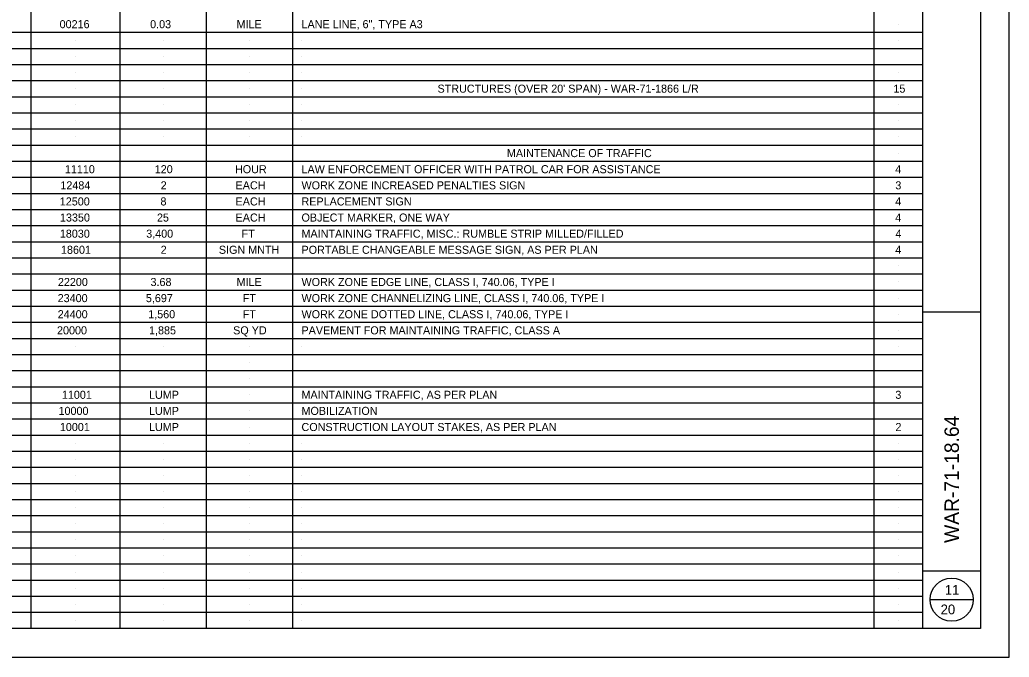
# Model space of a CAD drawing. Extents: x 1 to 35, y -2 to 20.
# Drawn here: x 17.83 to 35.03, y -1.96 to 9.12 of the extents above; entities that cross this region are included whole.
import ezdxf

# ---------------------------------------------------------------- set-up
doc = ezdxf.new("R2010")
doc.units = 0
for name, color, linetype in [('SH_Border', 7, 'Continuous'), ('SH_Cut_Line', 7, 'Continuous'), ('SH_Data', 7, 'Continuous'), ('SH_Text', 7, 'Continuous')]:
    doc.layers.add(name, color=color, linetype=linetype)

msp = doc.modelspace()

# ---------------------------------------------------------------- linework, layer by layer
at = {"layer": 'SH_Border'}
for p, q in [((33.531, -1.457), (33.531, 19.543)), ((33.531, 4.043), (34.531, 4.043)), ((33.531, -0.457), (34.531, -0.457))]:
    msp.add_line(p, q, dxfattribs=at)
msp.add_lwpolyline([(3.031, 19.543), (34.531, 19.543), (34.531, -1.457), (3.031, -1.457)], close=True, dxfattribs=at)
at = {"layer": 'SH_Cut_Line'}
msp.add_lwpolyline([(1.031, -1.957), (35.031, -1.957), (35.031, 20.043), (1.031, 20.043)], close=True, dxfattribs=at)
at = {"layer": 'SH_Data'}
for p, q in [((18.031, -1.457), (18.031, 19.543)), ((19.581, -1.457), (19.581, 19.543)), ((21.081, -1.457), (21.081, 19.543)), ((22.581, -1.457), (22.581, 19.543)), ((32.681, -1.457), (32.681, 19.543)), ((18.806, 9.043), (18.806, 9.043)), ((18.806, 9.043), (18.806, 9.043)), ((20.331, 9.043), (20.331, 9.043)), ((20.331, 9.043), (20.331, 9.043)), ((21.831, 9.043), (21.831, 9.043)), ((21.831, 9.043), (21.831, 9.043)), ((22.731, 9.043), (22.731, 9.043)), ((22.731, 9.043), (22.731, 9.043)), ((33.106, 9.043), (33.106, 9.043)), ((3.031, 8.903), (33.531, 8.903)), ((3.031, 8.623), (33.531, 8.623)), ((18.806, 8.763), (18.806, 8.763)), ((20.331, 8.763), (20.331, 8.763)), ((21.831, 8.763), (21.831, 8.763)), ((22.731, 8.763), (22.731, 8.763)), ((33.106, 8.763), (33.106, 8.763)), ((18.806, 8.483), (18.806, 8.483)), ((20.331, 8.483), (20.331, 8.483)), ((21.831, 8.483), (21.831, 8.483)), ((22.731, 8.483), (22.731, 8.483)), ((3.031, 8.343), (33.531, 8.343)), ((18.806, 8.203), (18.806, 8.203)), ((20.331, 8.203), (20.331, 8.203)), ((21.831, 8.203), (21.831, 8.203)), ((22.731, 8.203), (22.731, 8.203)), ((33.106, 8.203), (33.106, 8.203)), ((3.031, 8.063), (33.531, 8.063)), ((18.806, 7.923), (18.806, 7.923)), ((20.331, 7.923), (20.331, 7.923)), ((21.831, 7.923), (21.831, 7.923)), ((22.731, 7.923), (22.731, 7.923)), ((33.106, 7.923), (33.106, 7.923)), ((3.031, 7.783), (33.531, 7.783)), ((18.806, 7.643), (18.806, 7.643)), ((20.331, 7.643), (20.331, 7.643)), ((21.831, 7.643), (21.831, 7.643)), ((22.731, 7.643), (22.731, 7.643)), ((33.106, 7.643), (33.106, 7.643)), ((3.031, 7.503), (33.531, 7.503)), ((3.031, 7.223), (33.531, 7.223)), ((18.806, 7.363), (18.806, 7.363)), ((20.331, 7.363), (20.331, 7.363)), ((21.831, 7.363), (21.831, 7.363)), ((22.731, 7.363), (22.731, 7.363)), ((33.106, 7.363), (33.106, 7.363)), ((18.806, 7.083), (18.806, 7.083)), ((20.331, 7.083), (20.331, 7.083)), ((21.831, 7.083), (21.831, 7.083)), ((22.731, 7.083), (22.731, 7.083)), ((33.106, 7.083), (33.106, 7.083)), ((3.031, 6.943), (33.531, 6.943)), ((33.106, 6.803), (33.106, 6.803)), ((3.031, 6.663), (33.531, 6.663)), ((3.031, 6.383), (33.531, 6.383)), ((18.806, 6.523), (18.806, 6.523)), ((20.331, 6.523), (20.331, 6.523)), ((21.831, 6.523), (21.831, 6.523)), ((22.731, 6.523), (22.731, 6.523)), ((33.106, 6.523), (33.106, 6.523)), ((18.806, 6.243), (18.806, 6.243)), ((20.331, 6.243), (20.331, 6.243)), ((21.831, 6.243), (21.831, 6.243)), ((22.731, 6.243), (22.731, 6.243)), ((33.106, 6.243), (33.106, 6.243)), ((3.031, 6.103), (33.531, 6.103)), ((3.031, 5.823), (33.531, 5.823)), ((18.806, 5.683), (18.806, 5.683)), ((20.331, 5.683), (20.331, 5.683)), ((21.831, 5.683), (21.831, 5.683)), ((22.731, 5.683), (22.731, 5.683)), ((33.106, 5.683), (33.106, 5.683)), ((3.031, 5.543), (33.531, 5.543)), ((18.806, 5.403), (18.806, 5.403)), ((18.806, 5.403), (18.806, 5.403)), ((20.331, 5.403), (20.331, 5.403)), ((20.331, 5.403), (20.331, 5.403)), ((21.831, 5.403), (21.831, 5.403)), ((21.831, 5.403), (21.831, 5.403)), ((22.731, 5.403), (22.731, 5.403)), ((22.731, 5.403), (22.731, 5.403)), ((33.106, 5.403), (33.106, 5.403)), ((3.031, 5.263), (33.531, 5.263)), ((18.806, 5.123), (18.806, 5.123)), ((18.806, 5.123), (18.806, 5.123)), ((20.331, 5.123), (20.331, 5.123)), ((20.331, 5.123), (20.331, 5.123)), ((21.831, 5.123), (21.831, 5.123)), ((21.831, 5.123), (21.831, 5.123)), ((22.731, 5.123), (22.731, 5.123)), ((22.731, 5.123), (22.731, 5.123)), ((33.106, 5.123), (33.106, 5.123)), ((33.106, 5.123), (33.106, 5.123)), ((3.031, 4.983), (33.531, 4.983)), ((33.106, 4.843), (33.106, 4.843)), ((3.031, 4.703), (33.531, 4.703)), ((21.831, 4.563), (21.831, 4.563)), ((33.106, 4.563), (33.106, 4.563)), ((3.031, 4.423), (33.531, 4.423)), ((3.031, 4.143), (33.531, 4.143)), ((18.806, 4.283), (18.806, 4.283)), ((20.331, 4.283), (20.331, 4.283)), ((21.831, 4.283), (21.831, 4.283)), ((22.731, 4.283), (22.731, 4.283)), ((33.106, 4.283), (33.106, 4.283)), ((18.806, 4.003), (18.806, 4.003)), ((20.331, 4.003), (20.331, 4.003)), ((21.831, 4.003), (21.831, 4.003)), ((22.731, 4.003), (22.731, 4.003)), ((33.106, 4.003), (33.106, 4.003)), ((3.031, 3.863), (33.531, 3.863)), ((18.806, 3.723), (18.806, 3.723)), ((18.806, 3.723), (18.806, 3.723)), ((18.806, 3.723), (18.806, 3.723)), ((20.331, 3.723), (20.331, 3.723)), ((20.331, 3.723), (20.331, 3.723)), ((20.331, 3.723), (20.331, 3.723)), ((21.831, 3.723), (21.831, 3.723)), ((21.831, 3.723), (21.831, 3.723)), ((22.731, 3.723), (22.731, 3.723)), ((22.731, 3.723), (22.731, 3.723)), ((22.731, 3.723), (22.731, 3.723)), ((33.106, 3.723), (33.106, 3.723)), ((3.031, 3.583), (33.531, 3.583)), ((18.806, 3.443), (18.806, 3.443)), ((20.331, 3.443), (20.331, 3.443)), ((21.831, 3.443), (21.831, 3.443)), ((22.731, 3.443), (22.731, 3.443)), ((33.106, 3.443), (33.106, 3.443)), ((3.031, 3.303), (33.531, 3.303)), ((21.831, 3.163), (21.831, 3.163)), ((3.031, 3.023), (33.531, 3.023)), ((21.831, 2.883), (21.831, 2.883)), ((3.031, 2.743), (33.531, 2.743)), ((18.806, 2.603), (18.806, 2.603)), ((20.331, 2.603), (20.331, 2.603)), ((21.831, 2.603), (21.831, 2.603)), ((22.731, 2.603), (22.731, 2.603)), ((33.106, 2.603), (33.106, 2.603)), ((33.106, 2.603), (33.106, 2.603)), ((33.106, 2.603), (33.106, 2.603)), ((3.031, 2.463), (33.531, 2.463)), ((18.806, 2.323), (18.806, 2.323)), ((18.806, 2.323), (18.806, 2.323)), ((18.806, 2.323), (18.806, 2.323)), ((20.331, 2.323), (20.331, 2.323)), ((20.331, 2.323), (20.331, 2.323)), ((20.331, 2.323), (20.331, 2.323)), ((21.831, 2.323), (21.831, 2.323)), ((22.731, 2.323), (22.731, 2.323)), ((3.031, 2.183), (33.531, 2.183)), ((3.031, 1.903), (33.531, 1.903)), ((18.806, 2.043), (18.806, 2.043)), ((20.331, 2.043), (20.331, 2.043)), ((21.831, 2.043), (21.831, 2.043)), ((22.731, 2.043), (22.731, 2.043)), ((22.731, 2.043), (22.731, 2.043)), ((22.731, 2.043), (22.731, 2.043)), ((33.106, 2.043), (33.106, 2.043)), ((33.106, 2.043), (33.106, 2.043)), ((33.106, 2.043), (33.106, 2.043)), ((18.806, 1.763), (18.806, 1.763)), ((18.806, 1.763), (18.806, 1.763)), ((20.331, 1.763), (20.331, 1.763)), ((20.331, 1.763), (20.331, 1.763)), ((21.831, 1.763), (21.831, 1.763)), ((21.831, 1.763), (21.831, 1.763)), ((22.731, 1.763), (22.731, 1.763)), ((22.731, 1.763), (22.731, 1.763)), ((33.106, 1.763), (33.106, 1.763)), ((3.031, 1.623), (33.531, 1.623)), ((18.806, 1.483), (18.806, 1.483)), ((20.331, 1.483), (20.331, 1.483)), ((21.831, 1.483), (21.831, 1.483)), ((22.731, 1.483), (22.731, 1.483)), ((33.106, 1.483), (33.106, 1.483)), ((3.031, 1.343), (33.531, 1.343)), ((3.031, 1.063), (33.531, 1.063)), ((18.806, 1.203), (18.806, 1.203)), ((20.331, 1.203), (20.331, 1.203)), ((21.831, 1.203), (21.831, 1.203)), ((22.731, 1.203), (22.731, 1.203)), ((33.106, 1.203), (33.106, 1.203)), ((18.806, 0.923), (18.806, 0.923)), ((20.331, 0.923), (20.331, 0.923)), ((21.831, 0.923), (21.831, 0.923)), ((22.731, 0.923), (22.731, 0.923)), ((33.106, 0.923), (33.106, 0.923)), ((3.031, 0.783), (33.531, 0.783)), ((18.806, 0.643), (18.806, 0.643)), ((18.806, 0.643), (18.806, 0.643)), ((20.331, 0.643), (20.331, 0.643)), ((20.331, 0.643), (20.331, 0.643)), ((21.831, 0.643), (21.831, 0.643)), ((21.831, 0.643), (21.831, 0.643)), ((22.731, 0.643), (22.731, 0.643)), ((22.731, 0.643), (22.731, 0.643)), ((33.106, 0.643), (33.106, 0.643)), ((33.106, 0.643), (33.106, 0.643)), ((3.031, 0.503), (33.531, 0.503)), ((18.806, 0.363), (18.806, 0.363)), ((20.331, 0.363), (20.331, 0.363)), ((21.831, 0.363), (21.831, 0.363)), ((22.731, 0.363), (22.731, 0.363)), ((33.106, 0.363), (33.106, 0.363)), ((3.031, 0.223), (33.531, 0.223)), ((18.806, 0.083), (18.806, 0.083)), ((20.331, 0.083), (20.331, 0.083)), ((21.831, 0.083), (21.831, 0.083)), ((22.731, 0.083), (22.731, 0.083)), ((33.106, 0.083), (33.106, 0.083)), ((3.031, -0.057), (33.531, -0.057)), ((3.031, -0.337), (33.531, -0.337)), ((18.806, -0.197), (18.806, -0.197)), ((20.331, -0.197), (20.331, -0.197)), ((21.831, -0.197), (21.831, -0.197)), ((22.731, -0.197), (22.731, -0.197)), ((33.106, -0.197), (33.106, -0.197)), ((18.806, -0.477), (18.806, -0.477)), ((20.331, -0.477), (20.331, -0.477)), ((21.831, -0.477), (21.831, -0.477)), ((22.731, -0.477), (22.731, -0.477)), ((33.106, -0.477), (33.106, -0.477)), ((3.031, -0.617), (33.531, -0.617)), ((18.806, -0.757), (18.806, -0.757)), ((20.331, -0.757), (20.331, -0.757)), ((21.831, -0.757), (21.831, -0.757)), ((22.731, -0.757), (22.731, -0.757)), ((33.106, -0.757), (33.106, -0.757)), ((3.031, -0.897), (33.531, -0.897)), ((33.656, -0.957), (34.406, -0.957)), ((3.031, -1.177), (33.531, -1.177)), ((18.806, -1.037), (18.806, -1.037)), ((20.331, -1.037), (20.331, -1.037)), ((21.831, -1.037), (21.831, -1.037)), ((22.731, -1.037), (22.731, -1.037)), ((33.106, -1.037), (33.106, -1.037)), ((18.806, -1.317), (18.806, -1.317)), ((20.331, -1.317), (20.331, -1.317)), ((21.831, -1.317), (21.831, -1.317)), ((22.731, -1.317), (22.731, -1.317)), ((33.106, -1.317), (33.106, -1.317))]:
    msp.add_line(p, q, dxfattribs=at)
msp.add_circle((34.031, -0.957), 0.375, dxfattribs=at)

# ---------------------------------------------------------------- texts
msp.add_text('  WAR-71-18.64  ', height=0.25, rotation=90, dxfattribs=at).set_placement((34.156, -0.157))
for s, p in [(' 11 ', (33.849, -0.872)), (' 20 ', (33.776, -1.212))]:
    msp.add_text(s, height=0.17, dxfattribs=at).set_placement(p)
at = {"layer": 'SH_Text'}
for s, p in [('00216', (18.527, 8.973)), ('0.03', (20.1, 8.973)), ('LANE LINE, 6", TYPE A3', (22.731, 8.973)), ('MILE', (21.603, 8.973)), ("STRUCTURES (OVER 20' SPAN) - WAR-71-1866 L/R", (25.095, 7.853)), ('15', (33.018, 7.853)), ('MAINTENANCE OF TRAFFIC', (26.301, 6.733)), ('11110', (18.618, 6.453)), ('120', (20.18, 6.453)), ('HOUR', (21.575, 6.453)), ('LAW ENFORCEMENT OFFICER WITH PATROL CAR FOR ASSISTANCE', (22.731, 6.453)), ('4', (33.05, 6.453)), ('12484', (18.54, 6.173)), ('2', (20.283, 6.173)), ('EACH', (21.585, 6.173)), ('WORK ZONE INCREASED PENALTIES SIGN', (22.731, 6.173)), ('3', (33.052, 6.173)), ('12500', (18.53, 5.893)), ('8', (20.28, 5.893)), ('EACH', (21.585, 5.893)), ('REPLACEMENT SIGN', (22.731, 5.893)), ('4', (33.05, 5.893)), ('13350', (18.533, 5.613)), ('25', (20.219, 5.613)), ('EACH', (21.585, 5.613)), ('OBJECT MARKER, ONE WAY', (22.731, 5.613)), ('4', (33.05, 5.613)), ('18030', (18.531, 5.333)), ('3,400', (20.032, 5.333)), ('FT', (21.69, 5.333)), ('MAINTAINING TRAFFIC, MISC.: RUMBLE STRIP MILLED/FILLED', (22.731, 5.333)), ('4', (33.054, 5.333)), ('18601', (18.551, 5.053)), ('2', (20.283, 5.053)), ('SIGN MNTH', (21.295, 5.053)), ('SIGN MNTH', (21.295, 5.053)), ('PORTABLE CHANGEABLE MESSAGE SIGN, AS PER PLAN', (22.731, 5.053)), ('4', (33.05, 5.053)), ('22200', (18.497, 4.493)), ('3.68', (20.107, 4.493)), ('MILE', (21.603, 4.493)), ('WORK ZONE EDGE LINE, CLASS I, 740.06, TYPE I', (22.731, 4.493)), ('23400', (18.493, 4.213)), ('5,697', (20.026, 4.213)), ('FT', (21.709, 4.213)), ('WORK ZONE CHANNELIZING LINE, CLASS I, 740.06, TYPE I', (22.731, 4.213)), ('24400', (18.494, 3.933)), ('1,560', (20.067, 3.933)), ('FT', (21.709, 3.933)), ('WORK ZONE DOTTED LINE, CLASS I, 740.06, TYPE I', (22.731, 3.933)), ('20000', (18.482, 3.653)), ('1,885', (20.081, 3.653)), ('SQ YD', (21.543, 3.653)), ('PAVEMENT FOR MAINTAINING TRAFFIC, CLASS A', (22.731, 3.653)), ('11001', (18.566, 2.533)), ('LUMP', (20.08, 2.533)), ('MAINTAINING TRAFFIC, AS PER PLAN', (22.731, 2.533)), ('3', (33.052, 2.533)), ('10000', (18.508, 2.253)), ('LUMP', (20.08, 2.253)), ('MOBILIZATION', (22.731, 2.253)), ('10001', (18.531, 1.973)), ('LUMP', (20.08, 1.973)), ('CONSTRUCTION LAYOUT STAKES, AS PER PLAN', (22.731, 1.973)), ('2', (33.054, 1.973))]:
    msp.add_text(s, height=0.14, dxfattribs=at).set_placement(p)

doc.saveas('drawing.dxf')
